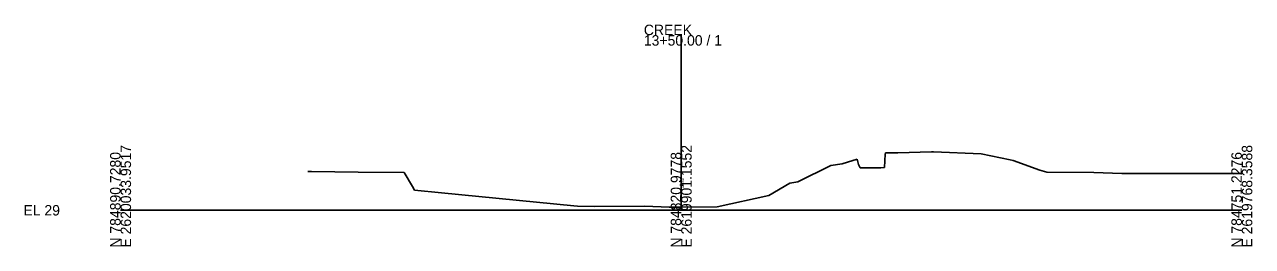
# Model space of a CAD drawing. Extents: x -26 to 303, y -10 to 5021.
# Drawn here: x -25.7 to 302.8, y 2990.3 to 3049.7 of the extents above; entities that cross this region are included whole.
import ezdxf

# ---------------------------------------------------------------- set-up
doc = ezdxf.new("R2010")
doc.units = 0
for name, color, linetype in [('RD_GPK_XS_Cell', 7, 'Continuous'), ('RD_XS_ExGround', 7, 'Continuous'), ('RD_XS_TX_Elev_EX', 7, 'Continuous')]:
    doc.layers.add(name, color=color, linetype=linetype)

msp = doc.modelspace()

# ---------------------------------------------------------------- linework, layer by layer
at = {"layer": 'RD_GPK_XS_Cell'}
for p, q in [((150, 3000), (150, 3046.9)), ((0, 3000), (150, 3000)), ((150, 3000), (300, 3000))]:
    msp.add_line(p, q, dxfattribs=at)
at = {"layer": 'RD_XS_ExGround'}
for p, q in [((193.08, 3012.47), (194.45, 3012.9)), ((194.45, 3012.9), (197.06, 3013.7)), ((197.06, 3013.7), (197.41, 3012.28)), ((204.38, 3011.41), (204.56, 3015.06)), ((204.56, 3015.06), (204.69, 3015.36)), ((204.69, 3015.36), (207.99, 3015.42)), ((207.99, 3015.42), (216.96, 3015.63)), ((216.96, 3015.63), (217.51, 3015.62)), ((217.51, 3015.62), (230.28, 3015.13)), ((230.28, 3015.13), (238, 3013.51)), ((238, 3013.51), (238.84, 3013.36)), ((238.84, 3013.36), (245.94, 3010.74)), ((50.14, 3010.34), (51.05, 3010.34)), ((51.05, 3010.34), (63.6, 3010.21)), ((63.6, 3010.21), (75.85, 3010.08)), ((75.85, 3010.08), (78.08, 3006.4)), ((181.21, 3007.61), (190.04, 3011.95)), ((190.04, 3011.95), (193.08, 3012.47)), ((197.41, 3012.28), (197.85, 3011.38)), ((197.85, 3011.38), (203.43, 3011.35)), ((203.43, 3011.35), (204.38, 3011.41)), ((245.94, 3010.74), (247.8, 3010.21)), ((247.8, 3010.21), (260.41, 3010.13)), ((260.41, 3010.13), (267.9, 3009.85)), ((267.9, 3009.85), (289.55, 3009.84)), ((289.55, 3009.84), (300, 3009.84)), ((78.08, 3006.4), (78.67, 3005.4)), ((173.49, 3003.92), (179.1, 3007.22)), ((179.1, 3007.22), (181.21, 3007.61)), ((78.67, 3005.4), (85.84, 3004.67)), ((85.84, 3004.67), (121.28, 3001.2)), ((159.6, 3000.91), (173.49, 3003.92)), ((121.28, 3001.2), (122.29, 3001.11)), ((122.29, 3001.11), (126.78, 3000.98)), ((126.78, 3000.98), (140.25, 3001.1)), ((140.25, 3001.1), (146.77, 3000.82)), ((146.77, 3000.82), (150, 3000.85)), ((150, 3000.85), (159.6, 3000.91))]:
    msp.add_line(p, q, dxfattribs=at)

# ---------------------------------------------------------------- texts
at = {"layer": 'RD_GPK_XS_Cell'}
for s, p in [('CREEK', (140, 3046.9)), ('13+50.00 / 1', (140, 3044.1)), ('EL 29', (-26, 2998.6))]:
    msp.add_text(s, height=2.8, dxfattribs=at).set_placement(p)
for s, p in [('E 2620033.9517', (2.8, 2990)), ('E 2619901.1552', (152.8, 2990)), ('E 2619768.3588', (302.8, 2990)), ('N 784890.7280', (0, 2990)), ('N 784820.9778', (150, 2990)), ('N 784751.2276', (300, 2990))]:
    msp.add_text(s, height=2.8, rotation=90, dxfattribs=at).set_placement(p)
at = {"layer": 'RD_XS_TX_Elev_EX'}
msp.add_text('29.85', height=0.8, rotation=90, dxfattribs=at).set_placement((150.7, 3005.85))

doc.saveas('drawing.dxf')
